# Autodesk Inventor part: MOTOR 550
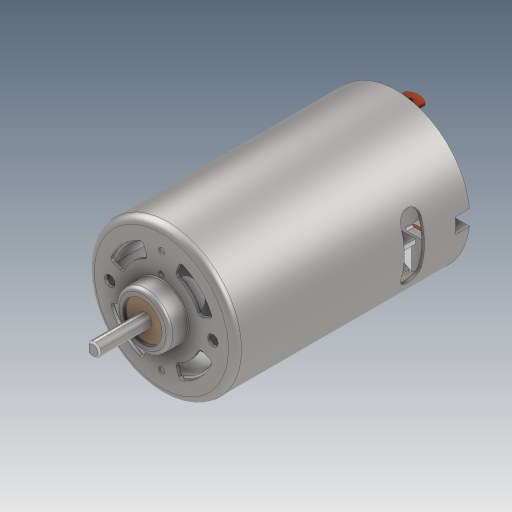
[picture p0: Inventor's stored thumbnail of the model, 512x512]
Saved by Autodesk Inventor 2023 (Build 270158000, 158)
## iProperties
Created: 2024-09
Part Number: MOTOR 550
Material: Generic
Document SubType Name: Modeling
Designer: kenda
Density: 1 g/cm^3
Appearance: Default
Author: kenda
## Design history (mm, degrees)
sketch "Sketch1"
  geometry: C1 r 17.856 at (0, 0); 1 further point
  constraints: 1 centre point, 1 coincident
  dimensions: "d0" = 35.7124 diameter of C1
extrude "Extrusion1" new body sketch "Sketch1" distance "d1" = 56.9468; taper "d2" = 0 deg
shell "Shell1" dims "d21" = 0.635
fillet "Fillet1" dims "d3" = 1.5875
sketch "Sketch2"
  geometry: C1 r 6.54 at (0, 0); 1 further point
  constraints: 1 centre point, 1 coincident
  dimensions: "d4" = 13.081 diameter of C1
extrude "Extrusion2" join sketch "Sketch2" distance "d5" = 4.572; taper "d6" = 0 deg
fillet "Fillet2" dims "d7" = 0.8255
sketch "Sketch3"
  geometry: C1 r 4.737 at (0, 0); 1 further point
  constraints: 1 centre point, 1 coincident
  dimensions: "d8" = 9.4742 diameter of C1
extrude "Extrusion3" cut sketch "Sketch3" distance "d9" = 0.6604; taper "d10" = 0 deg
sketch "Sketch4"
  geometry: C1 r 1.587 at (0, 0); 1 further point
  constraints: 1 centre point, 1 coincident
  dimensions: "d11" = 3.175 diameter of C1
extrude "Extrusion4" join sketch "Sketch4" distance "d12" = 12.7; taper "d13" = 0 deg
sketch "Sketch5"
  geometry: L1 (-0.953, 1.27)-(-0.953, -1.27); A1 r 1.587 centre (0, 0) between (-0.953, 1.27) and (-0.953, -1.27) reference; 2 further points
  constraints: 3 point on circle, 2 end point, 1 vertical
  dimensions: "d14" = 2.54 distance from line of point (1.587, 0) L1
extrude "Extrusion5" cut sketch "Sketch5" distance "d15" = 10.9728; taper "d16" = 0 deg
fillet "Fillet3" dims "d17" = 0.381
sketch "Sketch6"
  geometry: L1 (-12.522, 0)-(12.522, 0); C1 r 1.27 at (-12.522, 0); C2 r 1.27 at (12.522, 0); 2 further points
  constraints: 2 centre point, 2 coincident, 2 end point, 1 horizontal, 1 midpoint
  dimensions: "d18" = 2.54 diameter of C1; "d19" = 2.54 diameter of C2; "d20" = 25.0444 distance of L1.end L1.start
extrude "Extrusion6" cut sketch "Sketch6" distance "d22" = 0.635; taper "d23" = 0 deg
sketch "Sketch7"
  geometry: C1 r 0.672 at (0, 7.621); 1 further point
  constraints: 1 centre point
extrude "Extrusion7" cut sketch "Sketch7" distance "d24" = 0.635; taper "d25" = 0 deg
sketch "Sketch8"
  geometry: L1 (0, 0)-(6.107, 16.779); L2 (0, 0)-(16.779, 6.107); L3 (0, 0)-(0, 26.629); L4 (0, 0)-(26.704, 0); L5 (0, 0)-(-16.779, 6.107); L6 (0, 0)-(-6.107, 16.779); L7 (0, 0)-(-6.107, -16.779); L8 (0, 0)-(-16.779, -6.107); L9 (0, 0)-(16.779, -6.107); L10 (0, 0)-(6.107, -16.779); C1 r 13.233 at (0, 0); C2 r 1.587 at (0, 0) reference; A1 r 9.804 centre (0, 0) between (3.353, 9.213) and (9.213, 3.353); 21 further points
  constraints: 20 end point, 8 point on line, 2 centre point, 2 point on circle, 1 horizontal, 1 vertical, 33 other
  dimensions: "d26" = 4.6228 dimension on C1; "d27" = 3.429 radial gap between concentric circles of C1 A1; "d28" = 20 deg angle of L3 L1; "d29" = 20 deg angle of L4 L2; "d30" = 8.28704 distance of A1.end A1.start (derived); "d33" = 360 deg dimension on C1.centre L1.end (derived)
extrude "Extrusion8" cut sketch "Sketch8" distance "d35" = 0.635; taper "d36" = 0 deg
fillet "Fillet4" dims "d37" = 0.762
pattern_circular "Circular Pattern1" dims angle "d39" = 360 deg
sketch "Sketch9"
  geometry: L1 (0, 0)-(-16.804, -3.766); L2 (0, 0)-(-16.804, 3.766); L3 (0, 0)-(16.804, -3.766); L4 (0, 0)-(16.804, 3.766); C1 r 12.711 at (0, 0); C2 r 1.587 at (0, 0) reference; C3 r 17.099 at (0, 0); A1 r 17.221 centre (0, 0) between (-16.804, -3.766) and (-16.804, 3.766) reference; A2 r 1.207 centre (0, 0) between (0.953, 0.741) and (0.953, -0.741) reference; 9 further points
  constraints: 8 end point, 4 point on circle, 2 centre point, 2 point on line
extrude "IMAN" join sketch "Sketch9" distance "d41" = 35.56; taper "d42" = 0 deg
fillet "Fillet5" dims "d43" = 0.762
chamfer "Chamfer1" distance "d44" = 0.381; stored, may be unused: second distance "d45" = 3.175, angle "d46" = 45 deg
sketch "Sketch10"
  geometry: C1 r 1.27 at (-12.522, 0) reference; C2 r 16.269 at (0, 0) reference; C3 r 0.635 at (0, 12.522); C4 r 0.635 at (0, -12.522); 5 further points
  constraints: 3 coincident, 2 centre point, 5 other
  dimensions: "d49" = 360 deg dimension on C2.centre point (-12.522, 0) (derived); "d51" = 1.27 diameter of C4; "d52" = 1.27 diameter of C3
extrude "Extrusion10" cut sketch "Sketch10" distance "d53" = 0.254; taper "d54" = 0 deg
fillet "Fillet6" dims "d55" = 0.127
fillet "Fillet7" dims "d56" = 0.254
workplane "Work Plane1"
sketch "Sketch11"
  geometry: L1 (5.436, 13.424)-(-5.436, 13.424); L2 (5.436, 15.85)-(-5.436, 15.85); L3 (-5.436, 10.998)-(5.436, 10.998); L4 (17.856, 0)-(-17.856, 0) reference; A1 r 2.426 centre (5.436, 13.424) between (5.436, 10.998) and (5.436, 15.85); A2 r 2.426 centre (-5.436, 13.424) between (-5.436, 15.85) and (-5.436, 10.998); 5 further points
  constraints: 8 end point, 6 point on circle, 4 tangent, 2 centre point, 2 midpoint, 1 horizontal, 1 parallel, 1 vertical alignment
  dimensions: "d58" = 10.9982 distance between parallel lines of L4 L3; "d59" = 4.8514 distance between parallel lines of L3 L2; "d60" = 15.7226 distance of point (-7.861, 13.424) point (7.861, 13.424)
extrude "Extrusion11" cut sketch "Sketch11" stored distance "d61" = 0; taper "d62" = 0 deg
pattern_circular "Circular Pattern2" dims angle "d64" = 360 deg
sketch "Sketch12"
  geometry: C1 r 1.587 at (0, 0) reference; C2 r 3.361 at (0, 0); 1 further point
  constraints: 1 centre point, 1 coincident
extrude "Extrusion12" join sketch "Sketch12" distance "d66" = 6.6294; taper "d67" = 0 deg
sketch "Sketch13"
  geometry: C1 r 12.013 at (0, 0); 1 further point
  constraints: 1 centre point, 1 coincident
extrude "Extrusion13" join sketch "Sketch13" distance "d68" = 29.21; taper "d69" = 0 deg
sketch "Sketch14"
  geometry: C1 r 4.422 at (0, 0); 1 further point
  constraints: 1 centre point, 1 coincident
extrude "Extrusion14" join sketch "Sketch14" distance "d70" = 2.54; taper "d71" = 0 deg
sketch "Sketch15" dims "d73" = 32.5374, "d74" = 21.52215
  geometry: L1 (16.259, 0.572)-(10.746, 0.571); L2 (10.746, -0.571)-(16.259, -0.572); L3 (14.401, 7.569)-(9.434, 5.177); L4 (9.93, 4.148)-(14.897, 6.539); L5 (9.69, 13.068)-(6.253, 8.758); L6 (7.147, 8.045)-(10.584, 12.355); L7 (3.061, 15.978)-(1.834, 10.604); L8 (2.948, 10.349)-(4.175, 15.724); L9 (-4.175, 15.724)-(-2.948, 10.349); L10 (-1.834, 10.604)-(-3.061, 15.978); L11 (-10.584, 12.355)-(-7.147, 8.045); L12 (-6.253, 8.758)-(-9.69, 13.068); L13 (-14.897, 6.539)-(-9.93, 4.148); L14 (-9.434, 5.177)-(-14.401, 7.569); L15 (-16.259, -0.571)-(-10.746, -0.571); L16 (-10.746, 0.572)-(-16.259, 0.572); L17 (-14.401, -7.569)-(-9.434, -5.177); L18 (-9.93, -4.148)-(-14.897, -6.539); L19 (-9.69, -13.068)-(-6.253, -8.758); L20 (-7.147, -8.045)-(-10.584, -12.355); L21 (-3.061, -15.978)-(-1.834, -10.604); L22 (-2.948, -10.349)-(-4.175, -15.724); L23 (4.175, -15.724)-(2.948, -10.349); L24 (1.834, -10.604)-(3.061, -15.978); L25 (10.584, -12.355)-(7.147, -8.045); L26 (6.253, -8.758)-(9.69, -13.068); L27 (14.897, -6.539)-(9.93, -4.148); L28 (9.434, -5.177)-(14.401, -7.569); C1 r 3.361 at (0, 0) reference; 56 further points
  constraints: 56 end point, 2 coincident, 1 horizontal, 1 horizontal alignment, 1 parallel, 93 other
  dimensions: "d72" = 1.143 distance between parallel lines of L1 L2; "d77" = 360 deg dimension on point (0, 0) L1.start (derived)
extrude "Extrusion15" join sketch "Sketch15" distance "d79" = 5.08; taper "d80" = 0 deg
sketch "Sketch16"
  geometry: L1 (9.69, 13.068)-(6.253, 8.758) reference; L2 (7.147, 8.045)-(10.584, 12.355) reference; L3 (3.061, 15.978)-(1.834, 10.604) reference; L4 (2.948, 10.349)-(4.175, 15.724) reference; L5 (-4.175, 15.724)-(-2.948, 10.349) reference; L6 (-1.834, 10.604)-(-3.061, 15.978) reference; L7 (-10.584, 12.355)-(-7.147, 8.045) reference; L8 (-6.253, 8.758)-(-9.69, 13.068) reference; L9 (-14.897, 6.539)-(-9.93, 4.148) reference; L10 (-14.897, 6.539)-(-9.93, 4.148) reference; L11 (-9.434, 5.177)-(-14.401, 7.569) reference; L12 (-14.401, -7.569)-(-9.434, -5.177) reference; L13 (-9.93, -4.148)-(-14.897, -6.539) reference; L14 (-9.69, -13.068)-(-6.253, -8.758) reference; L15 (-7.147, -8.045)-(-10.584, -12.355) reference; L16 (-3.061, -15.978)-(-1.834, -10.604) reference; L17 (-2.948, -10.349)-(-4.175, -15.724) reference; L18 (4.175, -15.724)-(2.948, -10.349) reference; L19 (1.834, -10.604)-(3.061, -15.978) reference; L20 (10.584, -12.355)-(7.147, -8.045) reference; L21 (10.584, -12.355)-(7.147, -8.045) reference; L22 (6.253, -8.758)-(9.69, -13.068) reference; L23 (14.897, -6.539)-(9.93, -4.148) reference; L24 (9.434, -5.177)-(14.401, -7.569) reference; L25 (16.259, 0.572)-(10.746, 0.571) reference; L26 (10.746, -0.571)-(16.259, -0.572) reference; L27 (14.401, 7.569)-(9.434, 5.177) reference; L28 (9.93, 4.148)-(14.897, 6.539) reference; L29 (-16.259, -0.571)-(-10.746, -0.571) reference; L30 (-16.259, -0.571)-(-10.746, -0.571) reference; L31 (-10.746, 0.572)-(-16.259, 0.572) reference; C1 r 12.013 at (0, 0) reference; C2 r 1.27 at (12.522, 0) reference; A1 r 10.761 centre (0, 0) between (7.147, 8.045) and (6.253, 8.758) reference; A2 r 16.269 centre (0, 0) between (10.584, 12.355) and (9.69, 13.068) reference; A3 r 10.761 centre (0, 0) between (7.147, 8.045) and (6.253, 8.758) reference; A4 r 16.269 centre (0, 0) between (4.175, 15.724) and (3.061, 15.978) reference; A5 r 10.761 centre (0, 0) between (2.948, 10.349) and (1.834, 10.604) reference; A6 r 12.711 centre (0, 0) between (12.226, 3.476) and (-12.226, 3.476) reference; A7 r 16.269 centre (0, 0) between (-3.061, 15.978) and (-4.175, 15.724) reference; A8 r 10.761 centre (0, 0) between (-1.834, 10.604) and (-2.948, 10.349) reference; A9 r 16.269 centre (0, 0) between (-9.69, 13.068) and (-10.584, 12.355) reference; A10 r 10.761 centre (0, 0) between (-6.253, 8.758) and (-7.147, 8.045) reference; A11 r 16.269 centre (0, 0) between (-14.401, 7.569) and (-14.897, 6.539) reference; A12 r 10.761 centre (0, 0) between (-9.434, 5.177) and (-9.93, 4.148) reference; A13 r 12.711 centre (0, 0) between (-12.226, -3.476) and (12.226, -3.476) reference; A14 r 16.269 centre (0, 0) between (-14.897, -6.539) and (-14.401, -7.569) reference; A15 r 10.761 centre (0, 0) between (-9.93, -4.148) and (-9.434, -5.177) reference; A16 r 16.269 centre (0, 0) between (-10.584, -12.355) and (-9.69, -13.068) reference; A17 r 10.761 centre (0, 0) between (-7.147, -8.045) and (-6.253, -8.758) reference; A18 r 16.269 centre (0, 0) between (-4.175, -15.724) and (-3.061, -15.978) reference; A19 r 10.761 centre (0, 0) between (-2.948, -10.349) and (-1.834, -10.604) reference; A20 r 16.269 centre (0, 0) between (3.061, -15.978) and (4.175, -15.724) reference; A21 r 10.761 centre (0, 0) between (1.834, -10.604) and (2.948, -10.349) reference; A22 r 16.269 centre (0, 0) between (9.69, -13.068) and (10.584, -12.355) reference; A23 r 10.761 centre (0, 0) between (6.253, -8.758) and (7.147, -8.045) reference; A24 r 16.269 centre (0, 0) between (14.401, -7.569) and (14.897, -6.539) reference; A25 r 10.761 centre (0, 0) between (9.434, -5.177) and (9.93, -4.148) reference; A26 r 16.269 centre (0, 0) between (16.259, -0.572) and (16.259, 0.572) reference; A27 r 10.761 centre (0, 0) between (10.746, -0.571) and (10.746, 0.571) reference; A28 r 16.269 centre (0, 0) between (14.897, 6.539) and (14.401, 7.569) reference; A29 r 10.761 centre (0, 0) between (9.93, 4.148) and (9.434, 5.177) reference; A30 r 16.269 centre (0, 0) between (-16.259, 0.572) and (-16.259, -0.571) reference; A31 r 10.761 centre (0, 0) between (-10.746, 0.572) and (-10.746, -0.571) reference; 30 further points
  constraints: 1 coincident, 3 other
extrude "Extrusion16" join sketch "Sketch16" distance "d81" = 1.27; taper "d82" = 0 deg
sketch "Sketch17"
  geometry: C1 r 1.587 at (0, 0) reference; C2 r 5.144 at (0, 0); 1 further point
  constraints: 1 centre point, 1 coincident
extrude "Extrusion17" join sketch "Sketch17" distance "d83" = 4.445; taper "d84" = 0 deg
workplane "Work Plane2"
sketch "Sketch18"
  geometry: L1 (-17.856, 2.349)-(-12.522, 2.349); L2 (-12.522, 2.349)-(-12.522, -2.349); L3 (-12.522, -2.349)-(-17.856, -2.349); L4 (-17.856, -2.349)-(-17.856, 2.349); L5 (12.522, 2.349)-(17.856, 2.349); L6 (17.856, 2.349)-(17.856, -2.349); L7 (17.856, -2.349)-(12.522, -2.349); L8 (12.522, -2.349)-(12.522, 2.349); L9 (5.906, -10.998)-(-5.906, -10.998); L10 (-5.906, -10.998)-(-5.905, -17.856); L11 (-5.905, -17.856)-(5.905, -17.856); L12 (5.905, -17.856)-(5.906, -10.998); L13 (5.906, 10.998)-(5.906, 17.856); L14 (5.906, 17.856)-(-5.906, 17.856); L15 (-5.906, 10.998)-(5.906, 10.998); L16 (-5.906, 17.856)-(-5.906, 10.998); C1 r 17.628 at (0, 0); C2 r 17.856 at (0, 0) reference; A1 r 10.761 centre (0, 0) between (-6.253, 8.758) and (-7.147, 8.045) reference; 13 further points
  constraints: 32 end point, 8 parallel, 4 horizontal, 4 midpoint, 4 perpendicular, 4 tangent, 2 horizontal alignment, 2 vertical alignment, 1 centre point, 1 coincident
  dimensions: "d87" = 5.334 distance of L6.end L7.end; "d88" = 4.699 distance between parallel lines of L7 L5; "d89" = 4.699 distance between parallel lines of L3 L1; "d90" = 5.334 distance between parallel lines of L4 L2; "d92" = 11.811 distance between parallel lines of L10 L12; "d93" = 6.858 distance between parallel lines of L11 L9; "d95" = 11.811 distance between parallel lines of L16 L13; "d96" = 6.858 distance between parallel lines of L15 L14
extrude "Extrusion18" join sketch "Sketch18" distance "d97" = 0.635; taper "d98" = 0 deg
sketch "Sketch19"
  geometry: L1 (17.06, -2.349)-(12.522, -2.349) reference; L2 (12.522, -2.349)-(12.522, 2.349) reference; L3 (12.522, 2.349)-(17.06, 2.349) reference; L4 (5.906, 16.177)-(5.906, 10.998) reference; L5 (5.906, 10.998)-(-5.906, 10.998) reference; L6 (-5.906, 10.998)-(-5.906, 16.177) reference; L7 (-17.06, 2.349)-(-12.522, 2.349) reference; L8 (-12.522, 2.349)-(-12.522, -2.349) reference; L9 (-12.522, -2.349)-(-17.06, -2.349) reference; L10 (-5.905, -16.177)-(-5.906, -10.998) reference; L11 (-5.906, -10.998)-(5.906, -10.998) reference; L12 (5.906, -10.998)-(5.905, -16.177) reference; L13 (12.522, -2.349)-(18.13, -2.349); L14 (18.13, -2.349)-(18.13, 2.349); L15 (18.13, 2.349)-(12.522, 2.349); L16 (12.522, 2.349)-(12.522, -2.349); L17 (-17.06, -2.349)-(-12.522, -2.349) reference; L18 (-12.522, -2.349)-(-18.24, -2.349); L19 (-18.24, -2.349)-(-18.24, 2.349); L20 (-18.24, 2.349)-(-12.522, 2.349); L21 (-12.522, 2.349)-(-12.522, -2.349); A1 r 17.221 centre (0, 0) between (5.905, -16.177) and (17.06, -2.349) reference; A2 r 17.221 centre (0, 0) between (17.06, 2.349) and (5.906, 16.177) reference; A3 r 17.221 centre (0, 0) between (-5.906, 16.177) and (-17.06, 2.349) reference; A4 r 17.221 centre (0, 0) between (-17.06, -2.349) and (-5.905, -16.177) reference; 5 further points
  constraints: 16 end point, 4 parallel, 2 horizontal, 2 perpendicular, 1 point on line
extrude "Extrusion19" cut sketch "Sketch19" distance "d99" = 3.81; taper "d100" = 0 deg
sketch "Sketch20"
  geometry: L1 (17.06, -2.349)-(12.522, -2.349) reference; L2 (12.522, -2.349)-(12.522, 2.349) reference; L3 (12.522, 2.349)-(17.06, 2.349) reference; L4 (5.906, 16.177)-(5.906, 10.998) reference; L5 (5.906, 10.998)-(-5.906, 10.998) reference; L6 (-5.906, 10.998)-(-5.906, 16.177) reference; L7 (-17.06, 2.349)-(-12.522, 2.349) reference; L8 (-12.522, 2.349)-(-12.522, -2.349) reference; L9 (-12.522, -2.349)-(-17.06, -2.349) reference; L10 (-5.905, -16.177)-(-5.906, -10.998) reference; L11 (-5.906, -10.998)-(5.906, -10.998) reference; L12 (5.906, -10.998)-(5.905, -16.177) reference; L13 (10.859, -9.881)-(-10.859, -9.881); L14 (10.859, 9.881)-(-10.859, 9.881); A1 r 17.221 centre (0, 0) between (17.06, 2.349) and (-17.06, 2.349) reference; A2 r 17.221 centre (0, 0) between (-17.06, -2.349) and (17.06, -2.349) reference; A3 r 17.221 centre (0, 0) between (5.905, -16.177) and (17.06, -2.349) reference; A4 r 17.221 centre (0, 0) between (17.06, 2.349) and (5.906, 16.177) reference; A5 r 17.221 centre (0, 0) between (-5.906, 16.177) and (-17.06, 2.349) reference; A6 r 17.221 centre (0, 0) between (-17.06, -2.349) and (-5.905, -16.177) reference; A7 r 14.681 centre (0, 0) between (14.492, 2.349) and (10.859, 9.881); A8 r 14.681 centre (0, 0) between (-10.859, 9.881) and (-14.492, 2.35); A9 r 14.681 centre (0, 0) between (-14.492, -2.35) and (-10.859, -9.881); A10 r 14.681 centre (0, 0) between (10.859, -9.881) and (14.492, -2.35); 1 further point
  constraints: 8 point on circle, 4 centre point, 4 end point, 4 point on line, 2 horizontal
  dimensions: "d104" = 1.1176 distance between parallel lines of L11 L13; "d105" = 1.1176 distance between parallel lines of L5 L14
extrude "Extrusion20" join sketch "Sketch20" distance "d106" = 1.016; taper "d107" = 0 deg
fillet "Fillet8" dims "d108" = 1.016
sketch "Sketch21"
  geometry: C1 r 6.477 at (0, 0); 1 further point
  constraints: 1 centre point, 1 coincident
  dimensions: "d109" = 12.954 diameter of C1
extrude "Extrusion21" join sketch "Sketch21" distance "d110" = 4.1148; taper "d111" = 0 deg
fillet "Fillet9" dims "d112" = 1.016
sketch "Sketch22"
  geometry: C1 r 1.587 at (0, 0) reference; C2 r 4.966 at (0, 0); 1 further point
  constraints: 1 centre point, 1 coincident
  dimensions: "d113" = 9.9314 diameter of C2
extrude "Extrusion22" cut sketch "Sketch22" distance "d114" = 0.8382; taper "d115" = 0 deg
sketch "Sketch23"
  geometry: C1 r 1.587 at (0, 0); 1 further point
  constraints: 1 centre point, 1 coincident
  dimensions: "d116" = 3.175 diameter of C1
extrude "Extrusion23" join sketch "Sketch23" distance "d117" = 0.635; taper "d118" = 0 deg
fillet "Fillet10" dims "d119" = 0.381
sketch "Sketch24"
  geometry: L1 (-17.701, 2.349)-(-17.06, 2.349) reference; L2 (-12.522, -2.349)-(-13.462, -2.349) reference; L3 (-17.701, 2.349)-(-12.522, 2.349); L4 (-12.522, 2.349)-(-12.522, -2.349); L5 (-12.522, -2.349)-(-17.701, -2.349); L6 (-13.03, 1.841)-(-17.25, 1.842); L7 (-17.25, -1.841)-(-13.03, -1.841); L8 (-13.03, -1.841)-(-13.03, 1.841); L9 (-17.25, 1.842)-(-17.761, 1.842); L10 (-17.25, -1.841)-(-17.761, -1.841); A1 r 17.856 centre (0, 0) between (-17.701, 2.349) and (-17.701, -2.349) reference; A2 r 17.856 centre (0, 0) between (-17.701, 2.349) and (-17.701, -2.349) reference; 4 further points
  constraints: 16 end point, 3 parallel, 2 horizontal, 2 perpendicular, 2 point on circle, 1 other
  dimensions: "d120" = 0.508 distance between parallel lines of L3 L6
extrude "Extrusion24" join sketch "Sketch24" stored distance "d121" = 0.635; taper "d122" = 0 deg
sketch "Sketch25"
  geometry: L1 (-17.761, 1.842)-(-13.03, 1.841) reference; L2 (-13.03, -1.841)-(-17.761, -1.841) reference; L3 (-13.03, 1.841)-(-13.03, -1.841) reference; A1 r 17.856 centre (0, 0) between (-17.761, 1.842) and (-17.761, -1.841) reference; 1 further point
extrude "Extrusion25" join sketch "Sketch25" distance "d123" = 0.381; taper "d124" = 0 deg
pattern_circular "Circular Pattern3" dims angle "d126" = 360 deg
sketch "Sketch26"
  geometry: L1 (-10.008, 0)-(10.008, 0); C1 r 1.181 at (-10.008, 0); C2 r 1.181 at (10.008, 0); 2 further points
  constraints: 2 centre point, 2 coincident, 2 end point, 1 horizontal, 1 midpoint
  dimensions: "d128" = 2.3622 diameter of C1; "d129" = 2.3622 diameter of C2; "d130" = 20.0152 distance of L1.end L1.start
extrude "Extrusion26" cut sketch "Sketch26" distance "d131" = 2.794; taper "d132" = 0 deg
sketch "Sketch27"
  geometry: L1 (-8.166, -2.859)-(-11.8, -2.859); L2 (0, -22.878)-(0, 28.78); L3 (-24.702, 0)-(29.576, 0); L4 (-8.954, -8.199)-(-2.762, -8.199); L5 (-8.166, 2.859)-(-11.8, 2.859); L6 (-8.954, 8.199)-(-2.762, 8.199); L7 (8.954, -8.199)-(2.762, -8.199); L8 (8.166, -2.859)-(11.8, -2.859); L9 (8.166, 2.859)-(11.8, 2.859); L10 (8.954, 8.199)-(2.762, 8.199); C1 r 13.665 at (0, 0); A1 r 12.141 centre (0, 0) between (-8.954, -8.199) and (-11.8, -2.859); A2 r 8.652 centre (0, 0) between (-8.166, -2.859) and (-2.762, -8.199); 13 further points
  constraints: 20 end point, 12 symmetric about line, 4 point on circle, 3 centre point, 2 horizontal, 1 coincident, 1 parallel, 1 vertical
extrude "Extrusion27" cut sketch "Sketch27" distance "d133" = 2.794; taper "d134" = 0 deg
fillet "Fillet11" dims "d135" = 0.508
sketch "Sketch28"
  geometry: L1 (5.906, 16.177)-(5.906, 10.998) reference; L2 (5.906, 10.998)-(-5.906, 10.998) reference; L3 (-5.906, 10.998)-(-5.906, 16.177) reference; L4 (-5.906, -10.998)-(5.906, -10.998) reference; L5 (-11.183, -10.624)-(11.555, -10.624) reference; L6 (-15.245, -2.349)-(-17.06, -2.349) reference; L7 (-5.905, -16.177)-(-5.906, -10.998) reference; L8 (-5.906, -10.998)-(5.906, -10.998) reference; L9 (5.906, -10.998)-(5.905, -16.177) reference; L10 (17.06, -2.349)-(15.52, -2.349) reference; C1 r 17.221 at (0, 0) reference; A1 r 17.221 centre (0, 0) between (17.06, -2.349) and (17.06, 2.349) reference; A2 r 17.221 centre (0, 0) between (17.06, 2.349) and (5.906, 16.177) reference; A3 r 17.221 centre (0, 0) between (17.06, 2.349) and (5.906, 16.177) reference; A4 r 17.221 centre (0, 0) between (17.06, 2.349) and (-17.06, 2.349) reference; A5 r 17.221 centre (0, 0) between (-5.906, 16.177) and (-17.06, 2.349) reference; A6 r 17.221 centre (0, 0) between (-5.906, 16.177) and (-17.06, 2.349) reference; A7 r 17.221 centre (0, 0) between (-17.06, 2.349) and (-17.06, -2.349) reference; A8 r 17.221 centre (0, 0) between (-17.06, -2.349) and (-5.905, -16.177) reference; A9 r 17.221 centre (0, 0) between (-17.06, -2.349) and (-5.905, -16.177) reference; A10 r 17.221 centre (0, 0) between (-17.06, -2.349) and (17.06, -2.349) reference; A11 r 17.221 centre (0, 0) between (5.905, -16.177) and (17.06, -2.349) reference; A12 r 17.221 centre (0, 0) between (5.905, -16.177) and (17.06, -2.349) reference; A13 r 17.221 centre (0, 0) between (-16.341, 5.436) and (-16.341, -5.436) reference; A14 r 17.221 centre (0, 0) between (-16.341, 5.436) and (-16.341, -5.436) reference; A15 r 17.221 centre (0, 0) between (16.341, -5.436) and (16.341, 5.436) reference; A16 r 17.221 centre (0, 0) between (16.341, -5.436) and (16.341, 5.436) reference; A17 r 15.697 centre (0, 0) between (11.555, -10.624) and (15.52, -2.349) reference; A18 r 15.425 centre (0, 0) between (-15.245, -2.349) and (-11.183, -10.624) reference; A19 r 17.221 centre (0, 0) between (-17.06, -2.349) and (-5.905, -16.177) reference; A20 r 17.221 centre (0, 0) between (5.905, -16.177) and (17.06, -2.349) reference; 7 further points
extrude "Extrusion28" join sketch "Sketch28" stored distance "d136" = 1.016; taper "d137" = 0 deg
sketch "Sketch29"
  geometry: L1 (5.08, 14.834)-(-5.08, 14.834); L2 (-5.08, 14.834)-(-5.08, 12.776); L3 (-5.08, 12.776)-(5.08, 12.776); L4 (5.08, 12.776)-(5.08, 14.834); L5 (-5.906, 10.998)-(5.906, 10.998) reference; L6 (0, 0)-(-25.238, 0); L7 (-5.08, -12.776)-(5.08, -12.776); L8 (-5.08, -14.834)-(-5.08, -12.776); L9 (5.08, -14.834)-(-5.08, -14.834); L10 (5.08, -12.776)-(5.08, -14.834); C1 r 1.587 at (0, 0) reference; 3 further points
  constraints: 18 end point, 4 symmetric about line, 2 horizontal, 2 midpoint, 2 parallel, 1 perpendicular, 1 vertical alignment
  dimensions: "d138" = 1.778 distance between parallel lines of L5 L3; "d139" = 2.0574 distance between parallel lines of L3 L1; "d140" = 10.16 distance between parallel lines of L4 L2
extrude "Extrusion29" cut sketch "Sketch29" distance "d141" = 0.508; taper "d142" = 0 deg
sketch "Sketch30"
  geometry: L1 (-2.388, 13.538)-(2.388, 13.538); L2 (2.388, 13.538)-(2.388, 14.072); L3 (2.388, 14.072)-(-2.388, 14.072); L4 (-2.388, 14.072)-(-2.388, 13.538); L5 (-5.08, 12.776)-(-5.08, 14.834) reference; L6 (-5.08, 14.834)-(5.08, 14.834) reference; L7 (0, 0)-(-26.403, 0); L8 (-2.388, -13.538)-(2.388, -13.538); L9 (2.388, -13.538)-(2.388, -14.072); L10 (2.388, -14.072)-(-2.388, -14.072); L11 (-2.388, -14.072)-(-2.388, -13.538); 6 further points
  constraints: 18 end point, 6 symmetric about line, 4 midpoint, 2 horizontal, 2 parallel, 1 horizontal alignment, 1 perpendicular, 1 vertical alignment
  dimensions: "d143" = 4.7752 distance of L2.end L3.end; "d144" = 0.5334 distance between parallel lines of L3 L1
extrude "Extrusion30" join sketch "Sketch30" distance "d145" = 7.1374; taper "d146" = 0 deg
sketch "Sketch31"
  geometry: L1 (4.775, 0)-(4.775, 7.137) reference; L2 (0, 0)-(0, 7.137) reference; L3 (0, 7.137)-(4.775, 7.137) reference; L4 (2.377, 3.935)-(2.377, 4.832); L5 (8.865, 4.115)-(-4.089, 4.115) reference; L6 (1.744, 3.935)-(1.744, 4.832); L7 (3.01, 4.832)-(3.01, 3.935); A1 r 3.565 centre (2.388, 3.573) between (4.775, 6.22) and (0, 6.22); A2 r 0.633 centre (2.377, 3.935) between (1.744, 3.935) and (3.01, 3.935); A3 r 0.633 centre (2.377, 4.832) between (3.01, 4.832) and (1.744, 4.832); 3 further points
  constraints: 8 end point, 6 point on circle, 5 tangent, 3 centre point, 2 point on line, 1 midpoint, 1 parallel, 1 perpendicular
extrude "Extrusion31" cut sketch "Sketch31" stored distance "d147" = 7.1374; taper "d148" = 0 deg
pattern_circular "Circular Pattern4" dims angle "d150" = 360 deg
fillet "Fillet12" dims "d152" = 1.27
feature "સ耀઺耀઼耀ા耀ી耀ૂ耀ૄ耀૆耀" dims "d0" = 35.7124, "d1" = 56.9468, "d2" = 0, "d3" = 1.5875, "d4" = 13.081, "d5" = 4.572, "d6" = 0, "d7" = 0.8255, "d8" = 9.4742, "d9" = 0.6604, "d10" = 0, "d11" = 3.175, "d12" = 12.7, "d13" = 0, "d14" = 2.54, "d15" = 10.9728, "d16" = 0, "d17" = 0.381, "d18" = 2.54, "d19" = 2.54, "d20" = 25.0444, "d21" = 0.635, "d22" = 0.635, "d23" = 0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
body "Solid1"
node "Projected Loop1"
node "Projected Loop2"
node "Projected Loop3"
node "Projected Loop4"
node "Projected Loop5"
node "Projected Loop6"
node "Projected Loop7"
node "Projected Loop8"
node "Projected Loop9"
node "Projected Loop10"
node "Projected Loop11"
node "Projected Loop12"
node "Projected Loop13"
node "Projected Loop14"
node "Projected Loop15"
node "Projected Loop16"
node "Projected Loop17"
node "Projected Loop18"
